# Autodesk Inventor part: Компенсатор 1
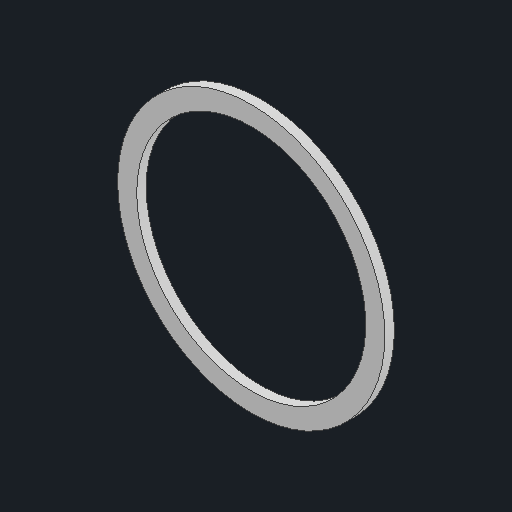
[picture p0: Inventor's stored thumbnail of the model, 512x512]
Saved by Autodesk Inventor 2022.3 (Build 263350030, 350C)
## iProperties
Created: 2020-09
Part Number: Компенсатор 1
Material: Типовые
Document SubType Name: Modeling
Designer: Карташов
Density: 1 g/cm^3
Appearance: По умолчанию
Title: D:\мои документы\Ирина\_WorldSkills\2020_09 ФНЧ\Module A\Участникам\GIVEN\Компенсатор 1.stp
Author: Дом
Sending System: Autodesk Inventor 2021
Preprocessor: ST-DEVELOPER v18.1
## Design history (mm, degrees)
feature "Твердое тело2"
node "Твердое тело1"
